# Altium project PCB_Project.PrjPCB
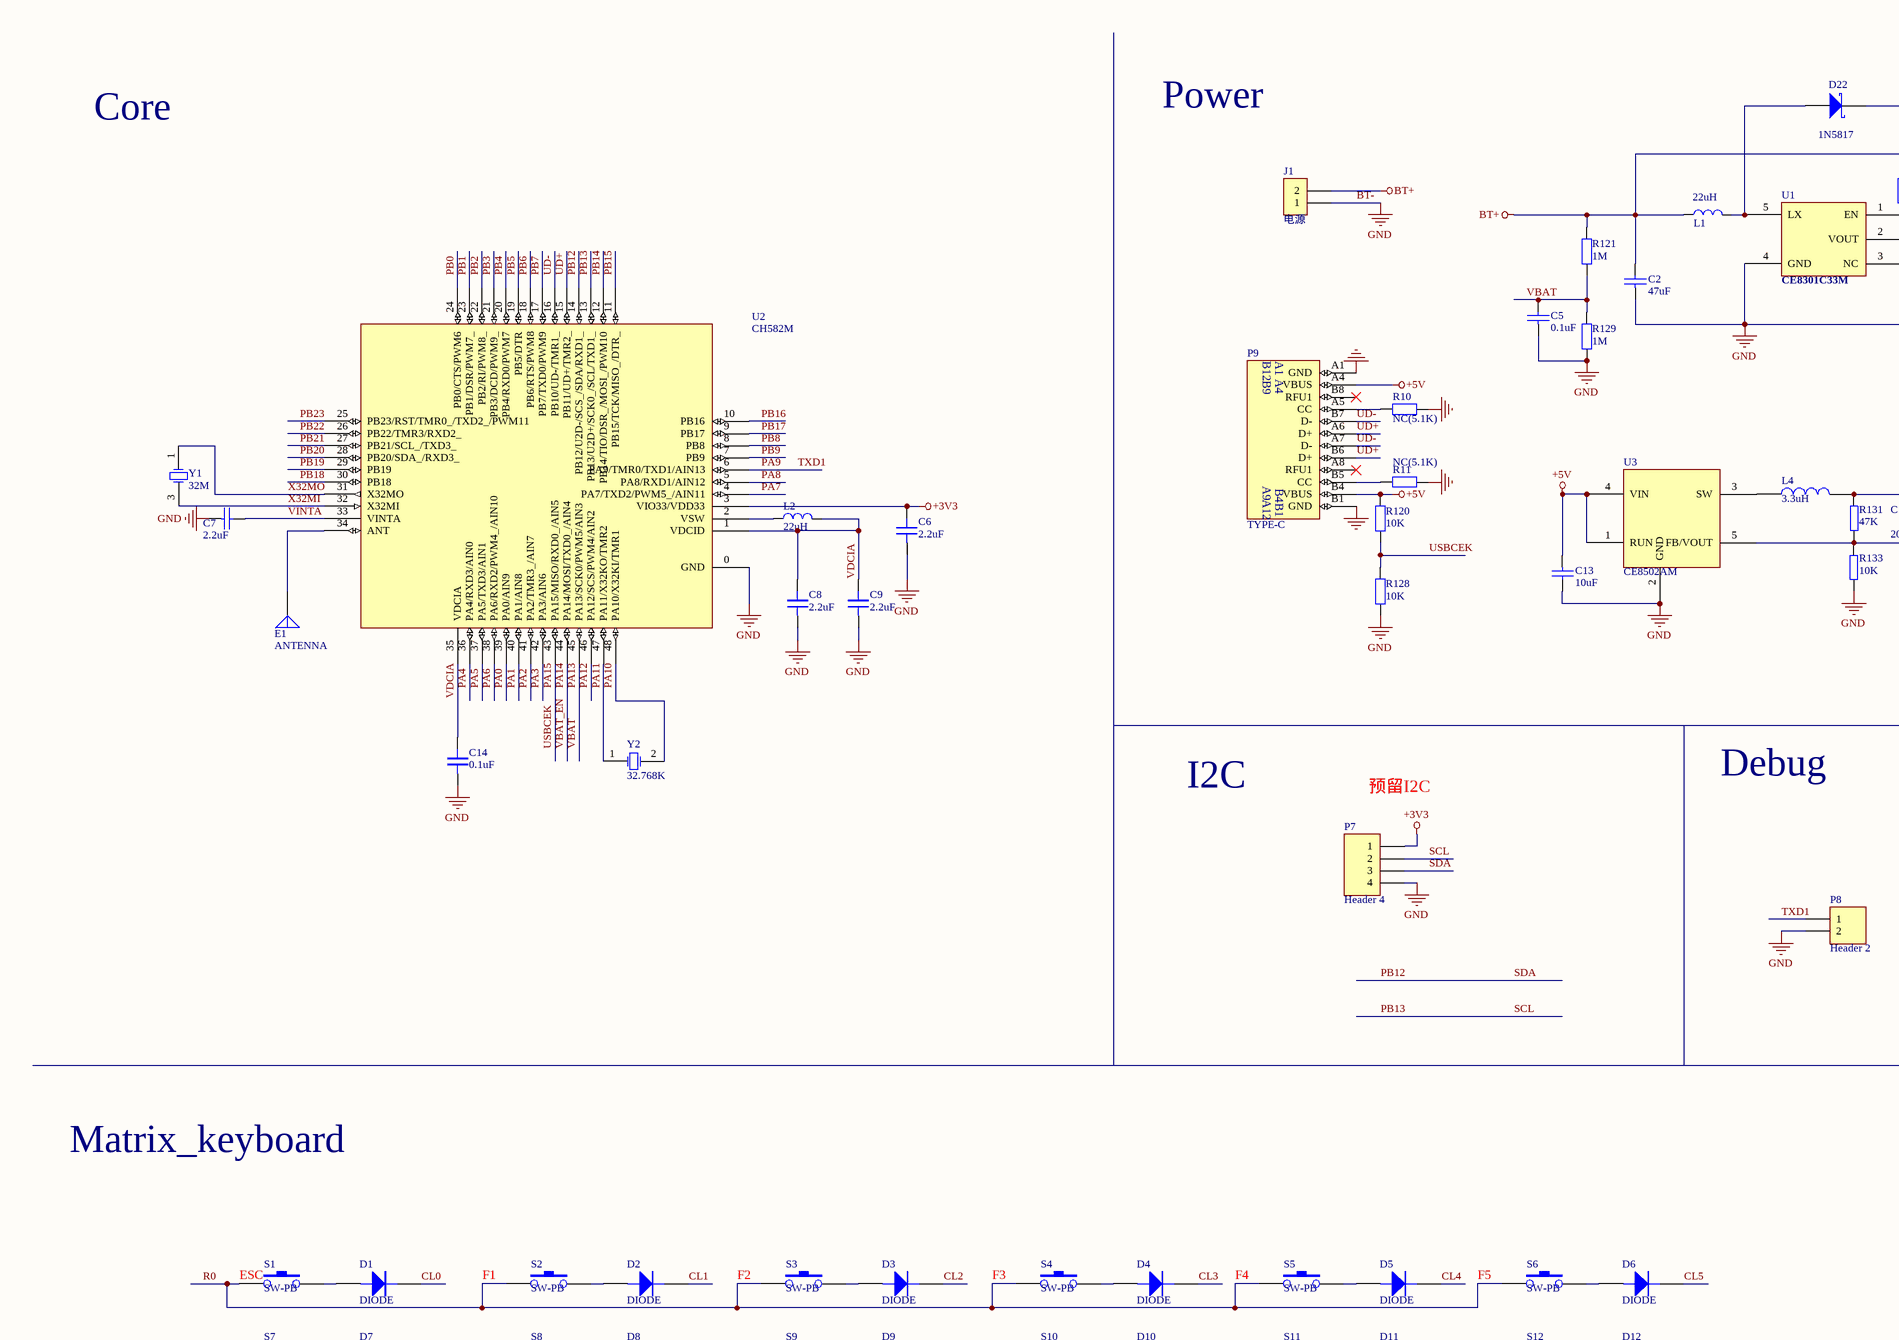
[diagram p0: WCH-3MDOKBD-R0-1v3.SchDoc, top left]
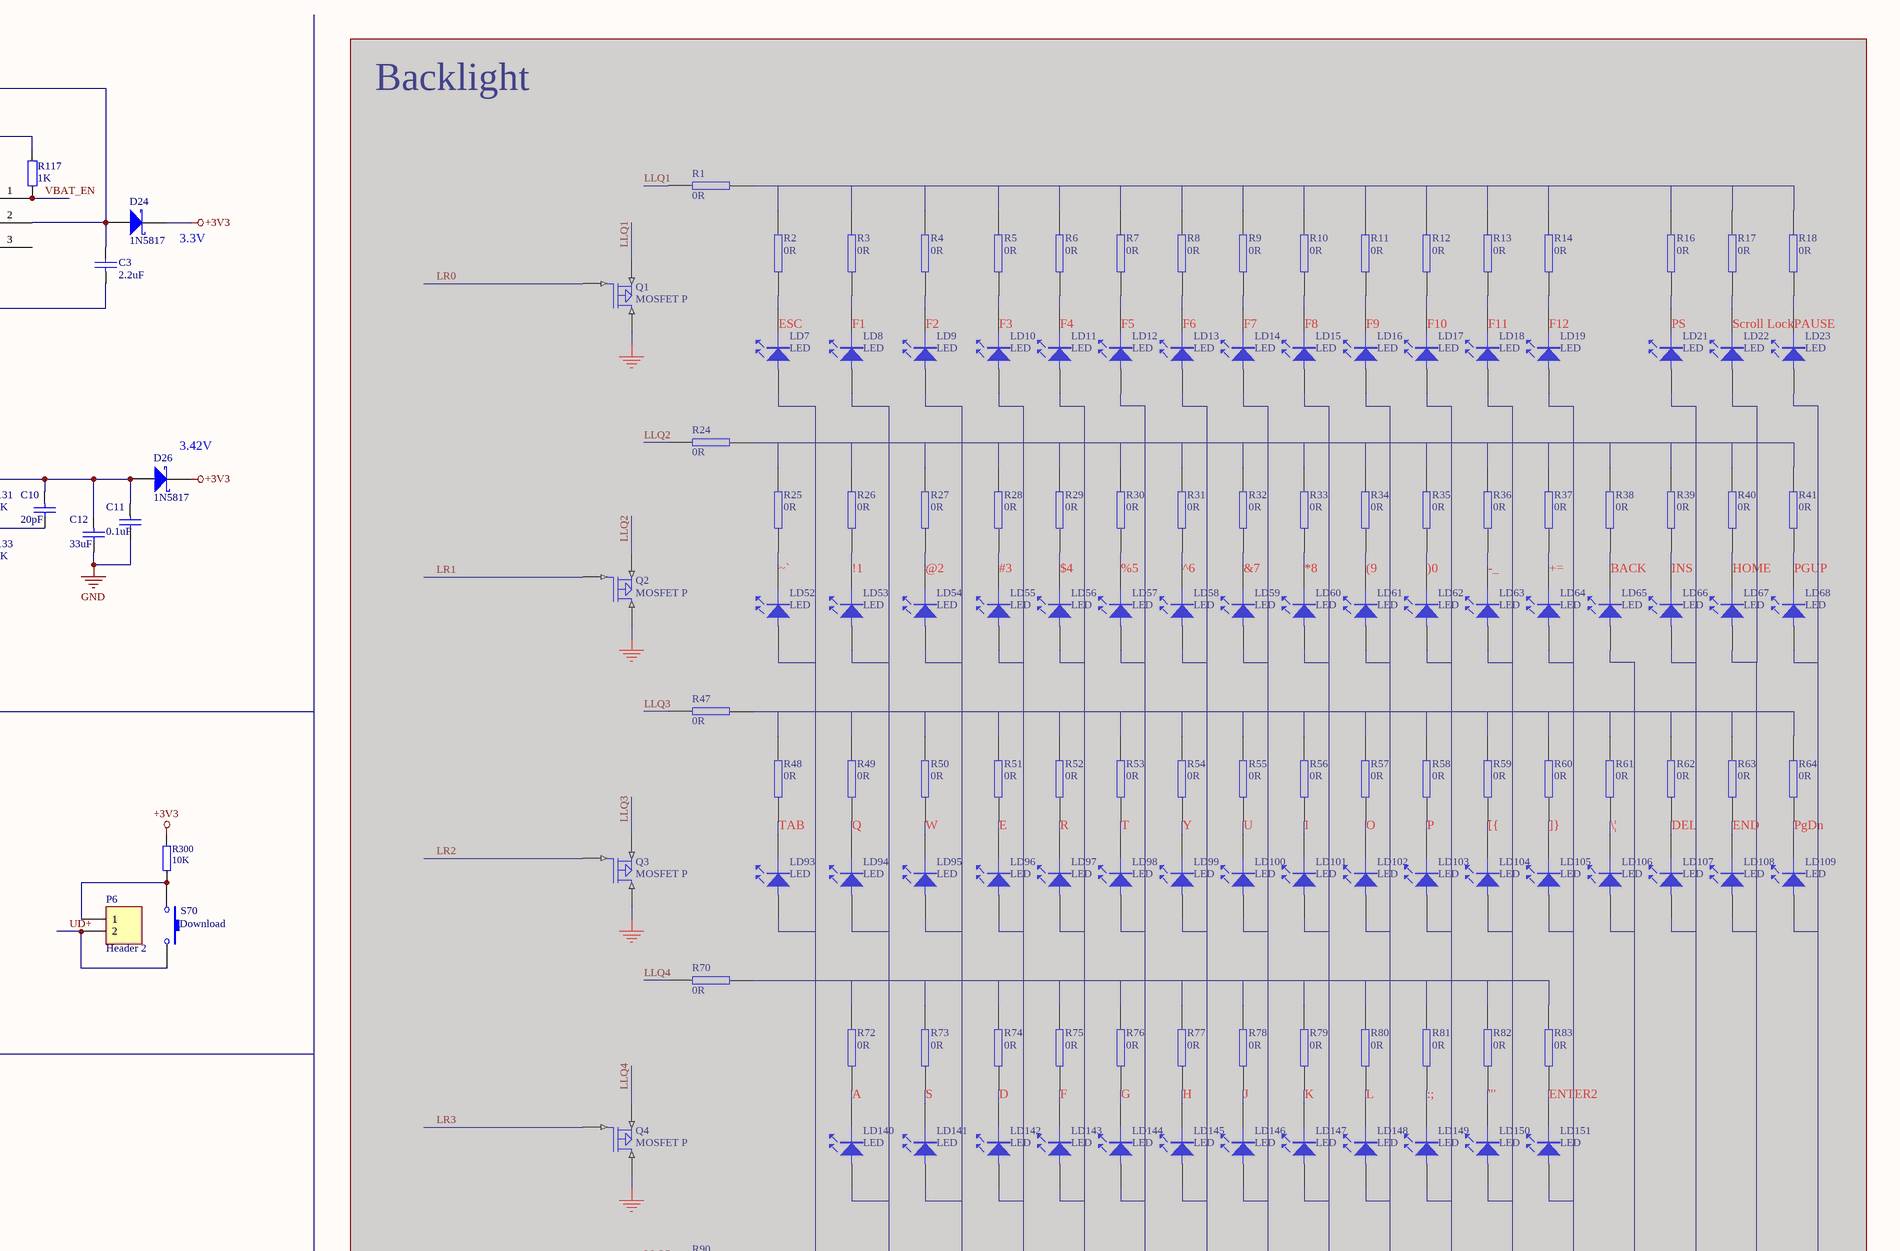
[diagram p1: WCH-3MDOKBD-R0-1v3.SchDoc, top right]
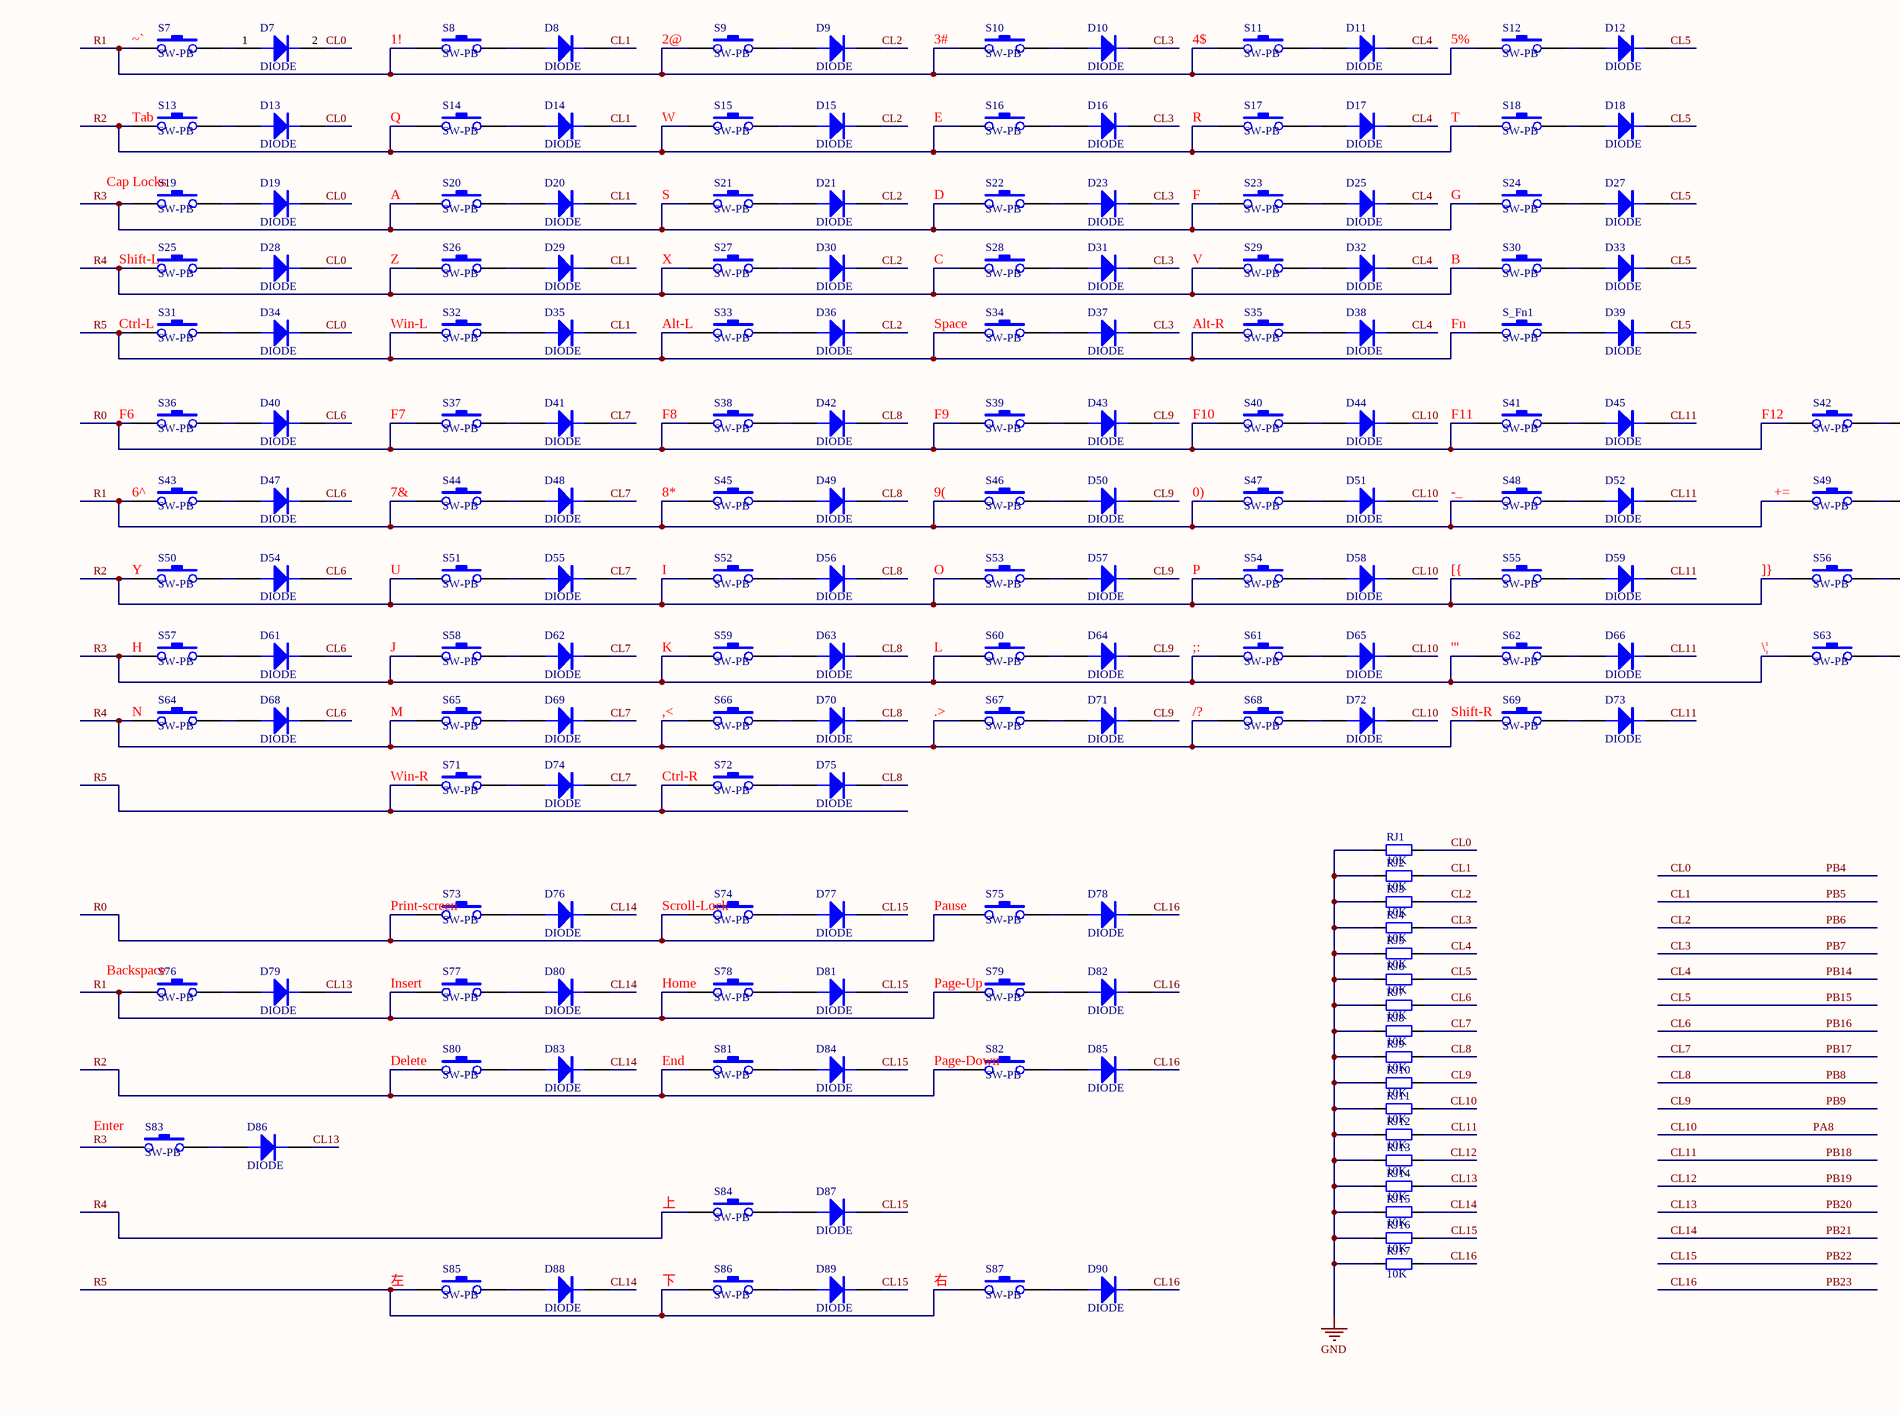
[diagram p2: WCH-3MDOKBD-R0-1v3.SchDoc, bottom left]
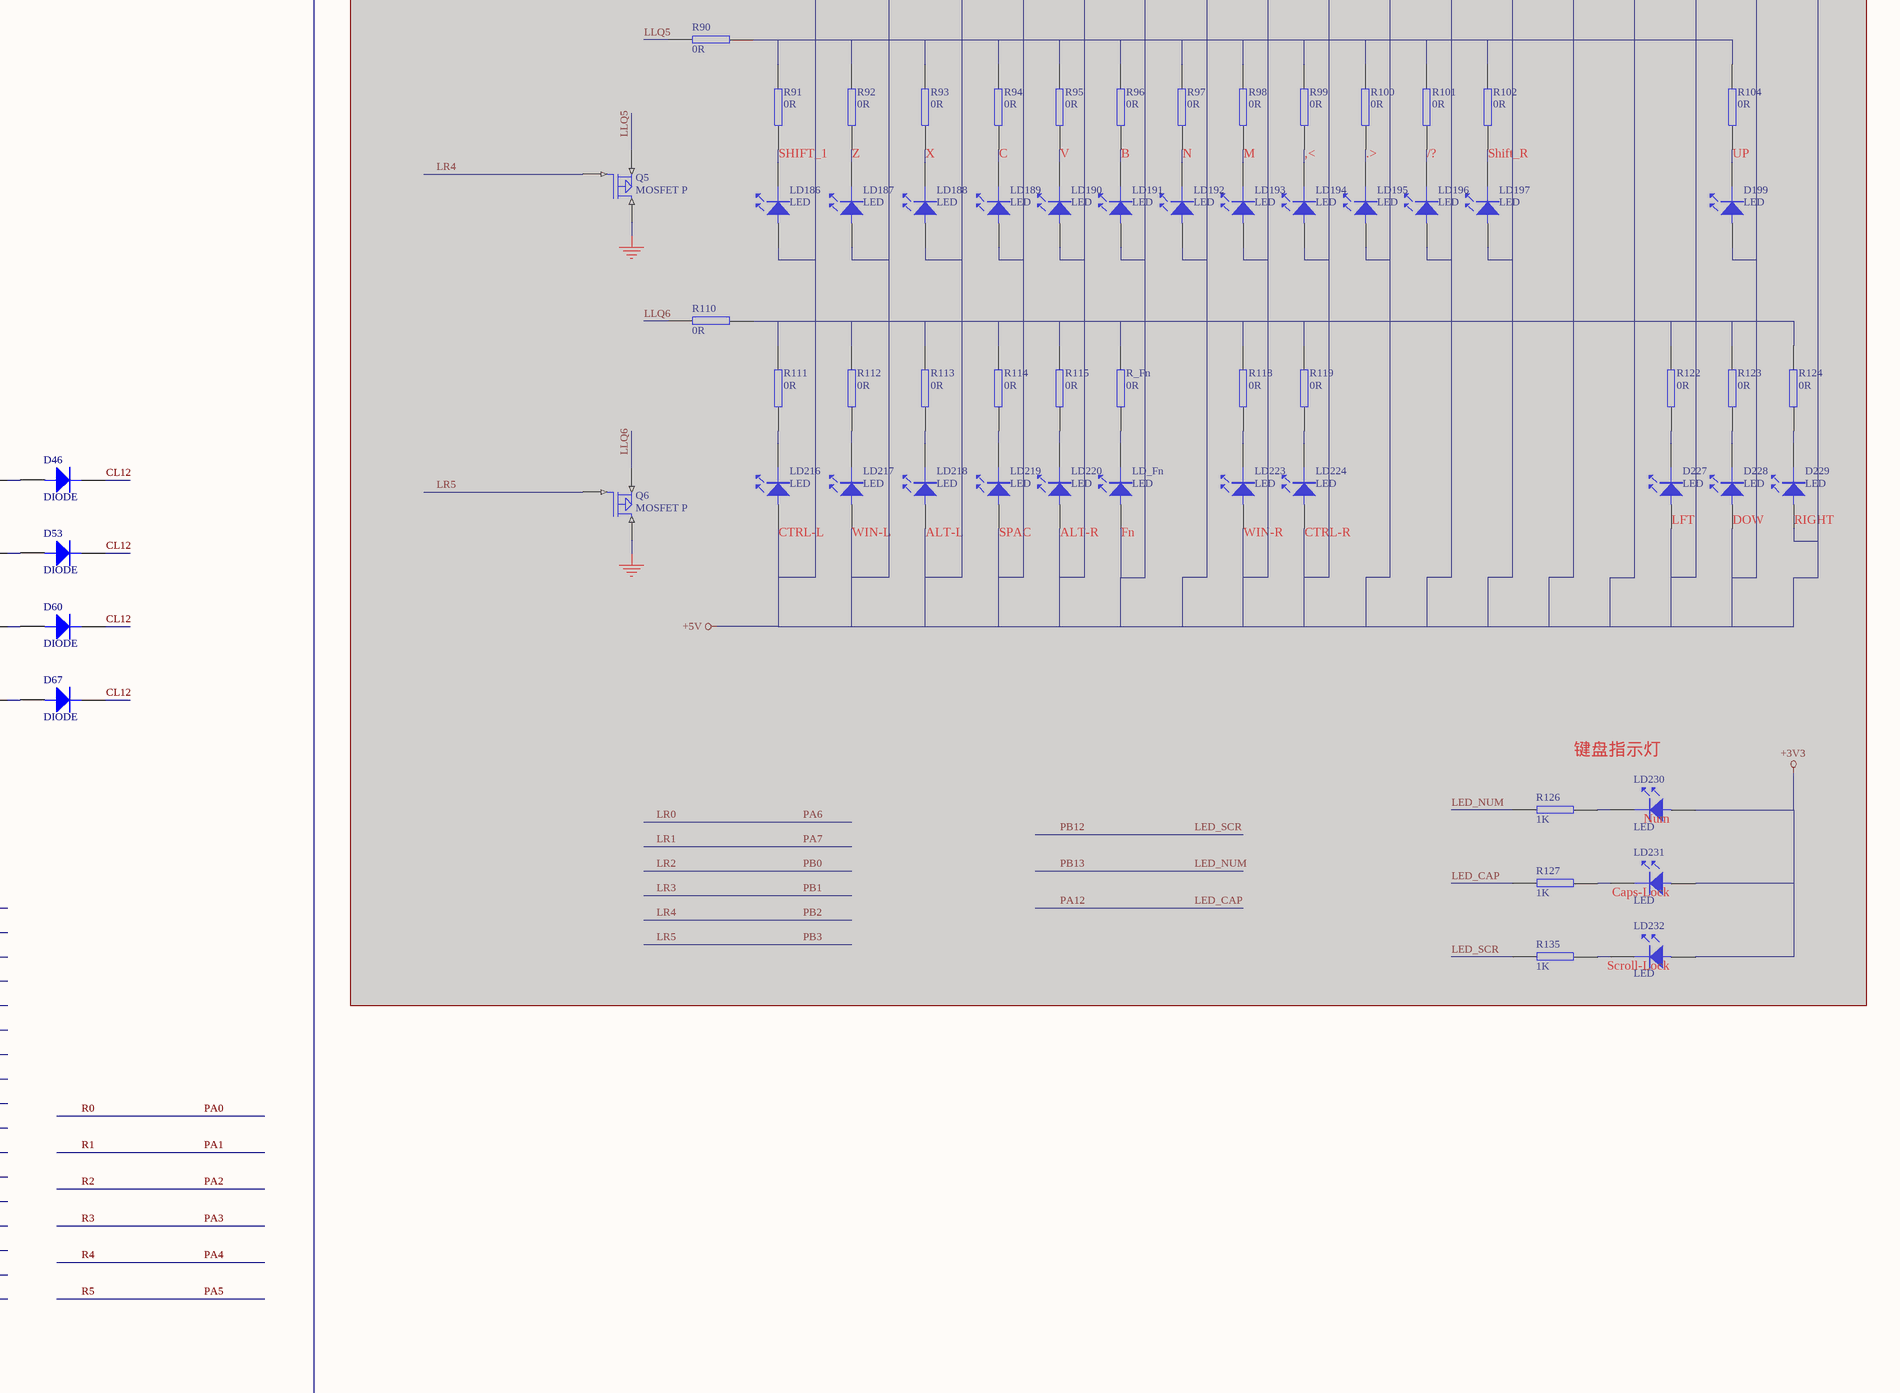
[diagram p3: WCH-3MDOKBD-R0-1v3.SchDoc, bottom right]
1 sheet, 421 parts. Net scope: global (net labels, ports and power ports of the same name join across sheets).
Board file: WCH-3MDOKBD-R0-1v3.PcbDoc

## Sheet WCH-3MDOKBD-R0-1v3.SchDoc
size A1

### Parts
(Parts that share a designator on the sheet are numbered #1, #2 ... from top to bottom, then left to right.)
C2  47uF  [3528_C]
C3  2.2uF  [0402_C]
C5  0.1uF  [0402_C]
C6  2.2uF  [0603_C]
C7  2.2uF  [0402_C]
C8  2.2uF  [0603_C]
C9  2.2uF  [0603_C]
C10  20pF  [0603_C]
C11  0.1uF  [0603_C]
C12  33uF  [3528_C]
C13  10uF  [3216_C]
C14  0.1uF  [0603_C]
D1  DIODE  [3216+]
D2  DIODE  [3216+]
D3  DIODE  [3216+]
D4  DIODE  [3216+]
D5  DIODE  [3216+]
D6  DIODE  [3216+]
D7  DIODE  [3216+]
D8  DIODE  [3216+]
D9  DIODE  [3216+]
D10  DIODE  [3216+]
D11  DIODE  [3216+]
D12  DIODE  [3216+]
D13  DIODE  [3216+]
D14  DIODE  [3216+]
D15  DIODE  [3216+]
D16  DIODE  [3216+]
D17  DIODE  [3216+]
D18  DIODE  [3216+]
D19  DIODE  [3216+]
D20  DIODE  [3216+]
D21  DIODE  [3216+]
D22  1N5817  [7227+]
D23  DIODE  [3216+]
D24  1N5817  [7227+]
D25  DIODE  [3216+]
D26  1N5817  [7227+]
D27  DIODE  [3216+]
D28  DIODE  [3216+]
D29  DIODE  [3216+]
D30  DIODE  [3216+]
D31  DIODE  [3216+]
D32  DIODE  [3216+]
D33  DIODE  [3216+]
D34  DIODE  [3216+]
D35  DIODE  [3216+]
D36  DIODE  [3216+]
D37  DIODE  [3216+]
D38  DIODE  [3216+]
D39  DIODE  [3216+]
D40  DIODE  [3216+]
D41  DIODE  [3216+]
D42  DIODE  [3216+]
D43  DIODE  [3216+]
D44  DIODE  [3216+]
D45  DIODE  [3216+]
D46  DIODE  [3216+]
D47  DIODE  [3216+]
D48  DIODE  [3216+]
D49  DIODE  [3216+]
D50  DIODE  [3216+]
D51  DIODE  [3216+]
D52  DIODE  [3216+]
D53  DIODE  [3216+]
D54  DIODE  [3216+]
D55  DIODE  [3216+]
D56  DIODE  [3216+]
D57  DIODE  [3216+]
D58  DIODE  [3216+]
D59  DIODE  [3216+]
D60  DIODE  [3216+]
D61  DIODE  [3216+]
D62  DIODE  [3216+]
D63  DIODE  [3216+]
D64  DIODE  [3216+]
D65  DIODE  [3216+]
D66  DIODE  [3216+]
D67  DIODE  [3216+]
D68  DIODE  [3216+]
D69  DIODE  [3216+]
D70  DIODE  [3216+]
D71  DIODE  [3216+]
D72  DIODE  [3216+]
D73  DIODE  [3216+]
D74  DIODE  [3216+]
D75  DIODE  [3216+]
D76  DIODE  [3216+]
D77  DIODE  [3216+]
D78  DIODE  [3216+]
D79  DIODE  [3216+]
D80  DIODE  [3216+]
D81  DIODE  [3216+]
D82  DIODE  [3216+]
D83  DIODE  [3216+]
D84  DIODE  [3216+]
D85  DIODE  [3216+]
D86  DIODE  [3216+]
D87  DIODE  [3216+]
D88  DIODE  [3216+]
D89  DIODE  [3216+]
D90  DIODE  [3216+]
D199  LED  [0603+]  (masked out: inside a compile mask, not in the netlist)
D227  LED  [0603+]  (masked out: inside a compile mask, not in the netlist)
D228  LED  [0603+]  (masked out: inside a compile mask, not in the netlist)
D229  LED  [0603+]  (masked out: inside a compile mask, not in the netlist)
E1  ANTENNA  [ANT-F-1-2.4G-1.6]
J1  电源  [SIP2-2.54mm]
L1  22uH  [SMD_7.3x7.8mm]
L2  22uH  [SMD_2x2mm]
L4  3.3uH  [SMD_5x5mm]
LD7  LED  [0603+]  (masked out: inside a compile mask, not in the netlist)
LD8  LED  [0603+]  (masked out: inside a compile mask, not in the netlist)
LD9  LED  [0603+]  (masked out: inside a compile mask, not in the netlist)
LD10  LED  [0603+]  (masked out: inside a compile mask, not in the netlist)
LD11  LED  [0603+]  (masked out: inside a compile mask, not in the netlist)
LD12  LED  [0603+]  (masked out: inside a compile mask, not in the netlist)
LD13  LED  [0603+]  (masked out: inside a compile mask, not in the netlist)
LD14  LED  [0603+]  (masked out: inside a compile mask, not in the netlist)
LD15  LED  [0603+]  (masked out: inside a compile mask, not in the netlist)
LD16  LED  [0603+]  (masked out: inside a compile mask, not in the netlist)
LD17  LED  [0603+]  (masked out: inside a compile mask, not in the netlist)
LD18  LED  [0603+]  (masked out: inside a compile mask, not in the netlist)
LD19  LED  [0603+]  (masked out: inside a compile mask, not in the netlist)
LD21  LED  [0603+]  (masked out: inside a compile mask, not in the netlist)
LD22  LED  [0603+]  (masked out: inside a compile mask, not in the netlist)
LD23  LED  [0603+]  (masked out: inside a compile mask, not in the netlist)
LD52  LED  [0603+]  (masked out: inside a compile mask, not in the netlist)
LD53  LED  [0603+]  (masked out: inside a compile mask, not in the netlist)
LD54  LED  [0603+]  (masked out: inside a compile mask, not in the netlist)
LD55  LED  [0603+]  (masked out: inside a compile mask, not in the netlist)
LD56  LED  [0603+]  (masked out: inside a compile mask, not in the netlist)
LD57  LED  [0603+]  (masked out: inside a compile mask, not in the netlist)
LD58  LED  [0603+]  (masked out: inside a compile mask, not in the netlist)
LD59  LED  [0603+]  (masked out: inside a compile mask, not in the netlist)
LD60  LED  [0603+]  (masked out: inside a compile mask, not in the netlist)
LD61  LED  [0603+]  (masked out: inside a compile mask, not in the netlist)
LD62  LED  [0603+]  (masked out: inside a compile mask, not in the netlist)
LD63  LED  [0603+]  (masked out: inside a compile mask, not in the netlist)
LD64  LED  [0603+]  (masked out: inside a compile mask, not in the netlist)
LD65  LED  [0603+]  (masked out: inside a compile mask, not in the netlist)
LD66  LED  [0603+]  (masked out: inside a compile mask, not in the netlist)
LD67  LED  [0603+]  (masked out: inside a compile mask, not in the netlist)
LD68  LED  [0603+]  (masked out: inside a compile mask, not in the netlist)
LD93  LED  [0603+]  (masked out: inside a compile mask, not in the netlist)
LD94  LED  [0603+]  (masked out: inside a compile mask, not in the netlist)
LD95  LED  [0603+]  (masked out: inside a compile mask, not in the netlist)
LD96  LED  [0603+]  (masked out: inside a compile mask, not in the netlist)
LD97  LED  [0603+]  (masked out: inside a compile mask, not in the netlist)
LD98  LED  [0603+]  (masked out: inside a compile mask, not in the netlist)
LD99  LED  [0603+]  (masked out: inside a compile mask, not in the netlist)
LD100  LED  [0603+]  (masked out: inside a compile mask, not in the netlist)
LD101  LED  [0603+]  (masked out: inside a compile mask, not in the netlist)
LD102  LED  [0603+]  (masked out: inside a compile mask, not in the netlist)
LD103  LED  [0603+]  (masked out: inside a compile mask, not in the netlist)
LD104  LED  [0603+]  (masked out: inside a compile mask, not in the netlist)
LD105  LED  [0603+]  (masked out: inside a compile mask, not in the netlist)
LD106  LED  [0603+]  (masked out: inside a compile mask, not in the netlist)
LD107  LED  [0603+]  (masked out: inside a compile mask, not in the netlist)
LD108  LED  [0603+]  (masked out: inside a compile mask, not in the netlist)
LD109  LED  [0603+]  (masked out: inside a compile mask, not in the netlist)
LD140  LED  [0603+]  (masked out: inside a compile mask, not in the netlist)
LD141  LED  [0603+]  (masked out: inside a compile mask, not in the netlist)
LD142  LED  [0603+]  (masked out: inside a compile mask, not in the netlist)
LD143  LED  [0603+]  (masked out: inside a compile mask, not in the netlist)
LD144  LED  [0603+]  (masked out: inside a compile mask, not in the netlist)
LD145  LED  [0603+]  (masked out: inside a compile mask, not in the netlist)
LD146  LED  [0603+]  (masked out: inside a compile mask, not in the netlist)
LD147  LED  [0603+]  (masked out: inside a compile mask, not in the netlist)
LD148  LED  [0603+]  (masked out: inside a compile mask, not in the netlist)
LD149  LED  [0603+]  (masked out: inside a compile mask, not in the netlist)
LD150  LED  [0603+]  (masked out: inside a compile mask, not in the netlist)
LD151  LED  [0603+]  (masked out: inside a compile mask, not in the netlist)
LD186  LED  [0603+]  (masked out: inside a compile mask, not in the netlist)
LD187  LED  [0603+]  (masked out: inside a compile mask, not in the netlist)
LD188  LED  [0603+]  (masked out: inside a compile mask, not in the netlist)
LD189  LED  [0603+]  (masked out: inside a compile mask, not in the netlist)
LD190  LED  [0603+]  (masked out: inside a compile mask, not in the netlist)
LD191  LED  [0603+]  (masked out: inside a compile mask, not in the netlist)
LD192  LED  [0603+]  (masked out: inside a compile mask, not in the netlist)
LD193  LED  [0603+]  (masked out: inside a compile mask, not in the netlist)
LD194  LED  [0603+]  (masked out: inside a compile mask, not in the netlist)
LD195  LED  [0603+]  (masked out: inside a compile mask, not in the netlist)
LD196  LED  [0603+]  (masked out: inside a compile mask, not in the netlist)
LD197  LED  [0603+]  (masked out: inside a compile mask, not in the netlist)
LD216  LED  [0603+]  (masked out: inside a compile mask, not in the netlist)
LD217  LED  [0603+]  (masked out: inside a compile mask, not in the netlist)
LD218  LED  [0603+]  (masked out: inside a compile mask, not in the netlist)
LD219  LED  [0603+]  (masked out: inside a compile mask, not in the netlist)
LD220  LED  [0603+]  (masked out: inside a compile mask, not in the netlist)
LD223  LED  [0603+]  (masked out: inside a compile mask, not in the netlist)
LD224  LED  [0603+]  (masked out: inside a compile mask, not in the netlist)
LD230  LED  [0603+]  (masked out: inside a compile mask, not in the netlist)
LD231  LED  [0603+]  (masked out: inside a compile mask, not in the netlist)
LD232  LED  [0603+]  (masked out: inside a compile mask, not in the netlist)
LD_Fn  LED  [0603+]  (masked out: inside a compile mask, not in the netlist)
P6  Header 2  [SIP2-2.54mm]
P7  Header 4  [HDR1X4]
P8  Header 2  [SIP2-2.54mm]
P9  TYPE-C  [TYPE-C-Receptacle-2.0]
Q1  MOSFET P  [SOT-23]  (masked out: inside a compile mask, not in the netlist)
Q2  MOSFET P  [SOT-23]  (masked out: inside a compile mask, not in the netlist)
Q3  MOSFET P  [SOT-23]  (masked out: inside a compile mask, not in the netlist)
Q4  MOSFET P  [SOT-23]  (masked out: inside a compile mask, not in the netlist)
Q5  MOSFET P  [SOT-23]  (masked out: inside a compile mask, not in the netlist)
Q6  MOSFET P  [SOT-23]  (masked out: inside a compile mask, not in the netlist)
R1  0R  [0603]  (masked out: inside a compile mask, not in the netlist)
R2  0R  [0603]  (masked out: inside a compile mask, not in the netlist)
R3  0R  [0603]  (masked out: inside a compile mask, not in the netlist)
R4  0R  [0603]  (masked out: inside a compile mask, not in the netlist)
R5  0R  [0603]  (masked out: inside a compile mask, not in the netlist)
R6  0R  [0603]  (masked out: inside a compile mask, not in the netlist)
R7  0R  [0603]  (masked out: inside a compile mask, not in the netlist)
R8  0R  [0603]  (masked out: inside a compile mask, not in the netlist)
R9  0R  [0603]  (masked out: inside a compile mask, not in the netlist)
R10#1  0R  [0603]  (masked out: inside a compile mask, not in the netlist)
R10#2  NC(5.1K)  [0603]
R11#1  0R  [0603]  (masked out: inside a compile mask, not in the netlist)
R11#2  NC(5.1K)  [0603]
R12  0R  [0603]  (masked out: inside a compile mask, not in the netlist)
R13  0R  [0603]  (masked out: inside a compile mask, not in the netlist)
R14  0R  [0603]  (masked out: inside a compile mask, not in the netlist)
R16  0R  [0603]  (masked out: inside a compile mask, not in the netlist)
R17  0R  [0603]  (masked out: inside a compile mask, not in the netlist)
R18  0R  [0603]  (masked out: inside a compile mask, not in the netlist)
R24  0R  [0603]  (masked out: inside a compile mask, not in the netlist)
R25  0R  [0603]  (masked out: inside a compile mask, not in the netlist)
R26  0R  [0603]  (masked out: inside a compile mask, not in the netlist)
R27  0R  [0603]  (masked out: inside a compile mask, not in the netlist)
R28  0R  [0603]  (masked out: inside a compile mask, not in the netlist)
R29  0R  [0603]  (masked out: inside a compile mask, not in the netlist)
R30  0R  [0603]  (masked out: inside a compile mask, not in the netlist)
R31  0R  [0603]  (masked out: inside a compile mask, not in the netlist)
R32  0R  [0603]  (masked out: inside a compile mask, not in the netlist)
R33  0R  [0603]  (masked out: inside a compile mask, not in the netlist)
R34  0R  [0603]  (masked out: inside a compile mask, not in the netlist)
R35  0R  [0603]  (masked out: inside a compile mask, not in the netlist)
R36  0R  [0603]  (masked out: inside a compile mask, not in the netlist)
R37  0R  [0603]  (masked out: inside a compile mask, not in the netlist)
R38  0R  [0603]  (masked out: inside a compile mask, not in the netlist)
R39  0R  [0603]  (masked out: inside a compile mask, not in the netlist)
R40  0R  [0603]  (masked out: inside a compile mask, not in the netlist)
R41  0R  [0603]  (masked out: inside a compile mask, not in the netlist)
R47  0R  [0603]  (masked out: inside a compile mask, not in the netlist)
R48  0R  [0603]  (masked out: inside a compile mask, not in the netlist)
R49  0R  [0603]  (masked out: inside a compile mask, not in the netlist)
R50  0R  [0603]  (masked out: inside a compile mask, not in the netlist)
R51  0R  [0603]  (masked out: inside a compile mask, not in the netlist)
R52  0R  [0603]  (masked out: inside a compile mask, not in the netlist)
R53  0R  [0603]  (masked out: inside a compile mask, not in the netlist)
R54  0R  [0603]  (masked out: inside a compile mask, not in the netlist)
R55  0R  [0603]  (masked out: inside a compile mask, not in the netlist)
R56  0R  [0603]  (masked out: inside a compile mask, not in the netlist)
R57  0R  [0603]  (masked out: inside a compile mask, not in the netlist)
R58  0R  [0603]  (masked out: inside a compile mask, not in the netlist)
R59  0R  [0603]  (masked out: inside a compile mask, not in the netlist)
R60  0R  [0603]  (masked out: inside a compile mask, not in the netlist)
R61  0R  [0603]  (masked out: inside a compile mask, not in the netlist)
R62  0R  [0603]  (masked out: inside a compile mask, not in the netlist)
R63  0R  [0603]  (masked out: inside a compile mask, not in the netlist)
R64  0R  [0603]  (masked out: inside a compile mask, not in the netlist)
R70  0R  [0603]  (masked out: inside a compile mask, not in the netlist)
R72  0R  [0603]  (masked out: inside a compile mask, not in the netlist)
R73  0R  [0603]  (masked out: inside a compile mask, not in the netlist)
R74  0R  [0603]  (masked out: inside a compile mask, not in the netlist)
R75  0R  [0603]  (masked out: inside a compile mask, not in the netlist)
R76  0R  [0603]  (masked out: inside a compile mask, not in the netlist)
R77  0R  [0603]  (masked out: inside a compile mask, not in the netlist)
R78  0R  [0603]  (masked out: inside a compile mask, not in the netlist)
R79  0R  [0603]  (masked out: inside a compile mask, not in the netlist)
R80  0R  [0603]  (masked out: inside a compile mask, not in the netlist)
R81  0R  [0603]  (masked out: inside a compile mask, not in the netlist)
R82  0R  [0603]  (masked out: inside a compile mask, not in the netlist)
R83  0R  [0603]  (masked out: inside a compile mask, not in the netlist)
R90  0R  [0603]  (masked out: inside a compile mask, not in the netlist)
R91  0R  [0603]  (masked out: inside a compile mask, not in the netlist)
R92  0R  [0603]  (masked out: inside a compile mask, not in the netlist)
R93  0R  [0603]  (masked out: inside a compile mask, not in the netlist)
R94  0R  [0603]  (masked out: inside a compile mask, not in the netlist)
R95  0R  [0603]  (masked out: inside a compile mask, not in the netlist)
R96  0R  [0603]  (masked out: inside a compile mask, not in the netlist)
R97  0R  [0603]  (masked out: inside a compile mask, not in the netlist)
R98  0R  [0603]  (masked out: inside a compile mask, not in the netlist)
R99  0R  [0603]  (masked out: inside a compile mask, not in the netlist)
R100  0R  [0603]  (masked out: inside a compile mask, not in the netlist)
R101  0R  [0603]  (masked out: inside a compile mask, not in the netlist)
R102  0R  [0603]  (masked out: inside a compile mask, not in the netlist)
R104  0R  [0603]  (masked out: inside a compile mask, not in the netlist)
R110  0R  [0603]  (masked out: inside a compile mask, not in the netlist)
R111  0R  [0603]  (masked out: inside a compile mask, not in the netlist)
R112  0R  [0603]  (masked out: inside a compile mask, not in the netlist)
R113  0R  [0603]  (masked out: inside a compile mask, not in the netlist)
R114  0R  [0603]  (masked out: inside a compile mask, not in the netlist)
R115  0R  [0603]  (masked out: inside a compile mask, not in the netlist)
R117  1K  [0603]
R118  0R  [0603]  (masked out: inside a compile mask, not in the netlist)
R119  0R  [0603]  (masked out: inside a compile mask, not in the netlist)
R120  10K  [0603]
R121  1M  [0603]
R122  0R  [0603]  (masked out: inside a compile mask, not in the netlist)
R123  0R  [0603]  (masked out: inside a compile mask, not in the netlist)
R124  0R  [0603]  (masked out: inside a compile mask, not in the netlist)
R126  1K  [0603]  (masked out: inside a compile mask, not in the netlist)
R127  1K  [0603]  (masked out: inside a compile mask, not in the netlist)
R128  10K  [0603]
R129  1M  [0603]
R131  47K  [0603]
R133  10K  [0603]
R135  1K  [0603]  (masked out: inside a compile mask, not in the netlist)
R300  10K  [0603]
R_Fn  0R  [0603]  (masked out: inside a compile mask, not in the netlist)
RJ1  10K  [0603]
RJ2  10K  [0603]
RJ3  10K  [0603]
RJ4  10K  [0603]
RJ5  10K  [0603]
RJ6  10K  [0603]
RJ7  10K  [0603]
RJ8  10K  [0603]
RJ9  10K  [0603]
RJ10  10K  [0603]
RJ11  10K  [0603]
RJ12  10K  [0603]
RJ13  10K  [0603]
RJ14  10K  [0603]
RJ15  10K  [0603]
RJ16  10K  [0603]
RJ17  10K  [0603]
S1  SW-PB  [SMD_6.1x3.65x2.5mm-KEY]
S2  SW-PB  [SMD_6.1x3.65x2.5mm-KEY]
S3  SW-PB  [SMD_6.1x3.65x2.5mm-KEY]
S4  SW-PB  [SMD_6.1x3.65x2.5mm-KEY]
S5  SW-PB  [SMD_6.1x3.65x2.5mm-KEY]
S6  SW-PB  [SMD_6.1x3.65x2.5mm-KEY]
S7  SW-PB  [SMD_6.1x3.65x2.5mm-KEY]
S8  SW-PB  [SMD_6.1x3.65x2.5mm-KEY]
S9  SW-PB  [SMD_6.1x3.65x2.5mm-KEY]
S10  SW-PB  [SMD_6.1x3.65x2.5mm-KEY]
S11  SW-PB  [SMD_6.1x3.65x2.5mm-KEY]
S12  SW-PB  [SMD_6.1x3.65x2.5mm-KEY]
S13  SW-PB  [SMD_6.1x3.65x2.5mm-KEY]
S14  SW-PB  [SMD_6.1x3.65x2.5mm-KEY]
S15  SW-PB  [SMD_6.1x3.65x2.5mm-KEY]
S16  SW-PB  [SMD_6.1x3.65x2.5mm-KEY]
S17  SW-PB  [SMD_6.1x3.65x2.5mm-KEY]
S18  SW-PB  [SMD_6.1x3.65x2.5mm-KEY]
S19  SW-PB  [SMD_6.1x3.65x2.5mm-KEY]
S20  SW-PB  [SMD_6.1x3.65x2.5mm-KEY]
S21  SW-PB  [SMD_6.1x3.65x2.5mm-KEY]
S22  SW-PB  [SMD_6.1x3.65x2.5mm-KEY]
S23  SW-PB  [SMD_6.1x3.65x2.5mm-KEY]
S24  SW-PB  [SMD_6.1x3.65x2.5mm-KEY]
S25  SW-PB  [SMD_6.1x3.65x2.5mm-KEY]
S26  SW-PB  [SMD_6.1x3.65x2.5mm-KEY]
S27  SW-PB  [SMD_6.1x3.65x2.5mm-KEY]
S28  SW-PB  [SMD_6.1x3.65x2.5mm-KEY]
S29  SW-PB  [SMD_6.1x3.65x2.5mm-KEY]
S30  SW-PB  [SMD_6.1x3.65x2.5mm-KEY]
S31  SW-PB  [SMD_6.1x3.65x2.5mm-KEY]
S32  SW-PB  [SMD_6.1x3.65x2.5mm-KEY]
S33  SW-PB  [SMD_6.1x3.65x2.5mm-KEY]
S34  SW-PB  [SMD_6.1x3.65x2.5mm-KEY]
S35  SW-PB  [SMD_6.1x3.65x2.5mm-KEY]
S36  SW-PB  [SMD_6.1x3.65x2.5mm-KEY]
S37  SW-PB  [SMD_6.1x3.65x2.5mm-KEY]
S38  SW-PB  [SMD_6.1x3.65x2.5mm-KEY]
S39  SW-PB  [SMD_6.1x3.65x2.5mm-KEY]
S40  SW-PB  [SMD_6.1x3.65x2.5mm-KEY]
S41  SW-PB  [SMD_6.1x3.65x2.5mm-KEY]
S42  SW-PB  [SMD_6.1x3.65x2.5mm-KEY]
S43  SW-PB  [SMD_6.1x3.65x2.5mm-KEY]
S44  SW-PB  [SMD_6.1x3.65x2.5mm-KEY]
S45  SW-PB  [SMD_6.1x3.65x2.5mm-KEY]
S46  SW-PB  [SMD_6.1x3.65x2.5mm-KEY]
S47  SW-PB  [SMD_6.1x3.65x2.5mm-KEY]
S48  SW-PB  [SMD_6.1x3.65x2.5mm-KEY]
S49  SW-PB  [SMD_6.1x3.65x2.5mm-KEY]
S50  SW-PB  [SMD_6.1x3.65x2.5mm-KEY]
S51  SW-PB  [SMD_6.1x3.65x2.5mm-KEY]
S52  SW-PB  [SMD_6.1x3.65x2.5mm-KEY]
S53  SW-PB  [SMD_6.1x3.65x2.5mm-KEY]
S54  SW-PB  [SMD_6.1x3.65x2.5mm-KEY]
S55  SW-PB  [SMD_6.1x3.65x2.5mm-KEY]
S56  SW-PB  [SMD_6.1x3.65x2.5mm-KEY]
S57  SW-PB  [SMD_6.1x3.65x2.5mm-KEY]
S58  SW-PB  [SMD_6.1x3.65x2.5mm-KEY]
S59  SW-PB  [SMD_6.1x3.65x2.5mm-KEY]
S60  SW-PB  [SMD_6.1x3.65x2.5mm-KEY]
S61  SW-PB  [SMD_6.1x3.65x2.5mm-KEY]
S62  SW-PB  [SMD_6.1x3.65x2.5mm-KEY]
S63  SW-PB  [SMD_6.1x3.65x2.5mm-KEY]
S64  SW-PB  [SMD_6.1x3.65x2.5mm-KEY]
S65  SW-PB  [SMD_6.1x3.65x2.5mm-KEY]
S66  SW-PB  [SMD_6.1x3.65x2.5mm-KEY]
S67  SW-PB  [SMD_6.1x3.65x2.5mm-KEY]
S68  SW-PB  [SMD_6.1x3.65x2.5mm-KEY]
S69  SW-PB  [SMD_6.1x3.65x2.5mm-KEY]
S70  Download  [贴片按键]
S71  SW-PB  [SMD_6.1x3.65x2.5mm-KEY]
S72  SW-PB  [SMD_6.1x3.65x2.5mm-KEY]
S73  SW-PB  [SMD_6.1x3.65x2.5mm-KEY]
S74  SW-PB  [SMD_6.1x3.65x2.5mm-KEY]
S75  SW-PB  [SMD_6.1x3.65x2.5mm-KEY]
S76  SW-PB  [SMD_6.1x3.65x2.5mm-KEY]
S77  SW-PB  [SMD_6.1x3.65x2.5mm-KEY]
S78  SW-PB  [SMD_6.1x3.65x2.5mm-KEY]
S79  SW-PB  [SMD_6.1x3.65x2.5mm-KEY]
S80  SW-PB  [SMD_6.1x3.65x2.5mm-KEY]
S81  SW-PB  [SMD_6.1x3.65x2.5mm-KEY]
S82  SW-PB  [SMD_6.1x3.65x2.5mm-KEY]
S83  SW-PB  [SMD_6.1x3.65x2.5mm-KEY]
S84  SW-PB  [SMD_6.1x3.65x2.5mm-KEY]
S85  SW-PB  [SMD_6.1x3.65x2.5mm-KEY]
S86  SW-PB  [SMD_6.1x3.65x2.5mm-KEY]
S87  SW-PB  [SMD_6.1x3.65x2.5mm-KEY]
S_Fn1  SW-PB  [SMD_6.1x3.65x2.5mm-KEY]
U1  CE8301C33M  [SOT-23-5]
U2  CH582M  [QFN48_5X5]
U3  CE8502AM  [SOT-23-5]
Y1  32M  [XT3225]
Y2  32.768K  [FC-135]

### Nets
+3V3: C6.2 D24.2(K) D26.2(K) P7.1 R300.2 U2.3(VIO33/VDD33)
+5V: C13.1 P9.A4(VBUS) P9.B4(VBUS) R120.2 U3.1(RUN) U3.4(VIN)
BT+: C2.2 J1.2 L1.1 R117.2 R121.2
BT-: C2.1 C3.1 C5.1 C6.1 C7.1 C8.1 C9.1 C11.2 C12.2 C13.2 C14.1 J1.1 P7.4 P8.2 P9.A1(GND) P9.B1(GND) R10#2.2 R11#2.2 R128.1 R129.1 R133.1 RJ1.1 RJ2.1 RJ3.1 RJ4.1 RJ5.1 RJ6.1 RJ7.1 RJ8.1 RJ9.1 RJ10.1 RJ11.1 RJ12.1 RJ13.1 RJ14.1 RJ15.1 RJ16.1 RJ17.1 U1.4(GND) U2.0(GND) U3.2(GND)  [also labelled GND]
CL0: D1.2(K) D7.2(K) D13.2(K) D19.2(K) D28.2(K) D34.2(K) RJ1.2 U2.20(PB4/RXD0/PWM7)  [also labelled PB4]
CL1: D2.2(K) D8.2(K) D14.2(K) D20.2(K) D29.2(K) D35.2(K) RJ2.2 U2.19(PB5/DTR)  [also labelled PB5]
CL2: D3.2(K) D9.2(K) D15.2(K) D21.2(K) D30.2(K) D36.2(K) RJ3.2 U2.18(PB6/RTS/PWM8)  [also labelled PB6]
CL3: D4.2(K) D10.2(K) D16.2(K) D23.2(K) D31.2(K) D37.2(K) RJ4.2 U2.17(PB7/TXD0/PWM9)  [also labelled PB7]
CL4: D5.2(K) D11.2(K) D17.2(K) D25.2(K) D32.2(K) D38.2(K) RJ5.2 U2.12(PB14/TIO/DSR_/MOSI_/PWM10)  [also labelled PB14]
CL5: D6.2(K) D12.2(K) D18.2(K) D27.2(K) D33.2(K) D39.2(K) RJ6.2 U2.11(PB15/TCK/MISO_/DTR_)  [also labelled PB15]
CL6: D40.2(K) D47.2(K) D54.2(K) D61.2(K) D68.2(K) RJ7.2 U2.10(PB16)  [also labelled PB16]
CL7: D41.2(K) D48.2(K) D55.2(K) D62.2(K) D69.2(K) D74.2(K) RJ8.2 U2.9(PB17)  [also labelled PB17]
CL8: D42.2(K) D49.2(K) D56.2(K) D63.2(K) D70.2(K) D75.2(K) RJ9.2 U2.8(PB8)  [also labelled PB8]
CL9: D43.2(K) D50.2(K) D57.2(K) D64.2(K) D71.2(K) RJ10.2 U2.7(PB9)  [also labelled PB9]
CL10: D44.2(K) D51.2(K) D58.2(K) D65.2(K) D72.2(K) RJ11.2 U2.5(PA8/RXD1/AIN12)  [also labelled PA8]
CL11: D45.2(K) D52.2(K) D59.2(K) D66.2(K) D73.2(K) RJ12.2 U2.30(PB18)  [also labelled PB18]
CL12: D46.2(K) D53.2(K) D60.2(K) D67.2(K) RJ13.2 U2.29(PB19)  [also labelled PB19]
CL13: D79.2(K) D86.2(K) RJ14.2 U2.28(PB20/SDA_/RXD3_)  [also labelled PB20]
CL14: D76.2(K) D80.2(K) D83.2(K) D88.2(K) RJ15.2 U2.27(PB21/SCL_/TXD3_)  [also labelled PB21]
CL15: D77.2(K) D81.2(K) D84.2(K) D87.2(K) D89.2(K) RJ16.2 U2.26(PB22/TMR3/RXD2_)  [also labelled PB22]
CL16: D78.2(K) D82.2(K) D85.2(K) D90.2(K) RJ17.2 U2.25(PB23/RST/TMR0_/TXD2_/PWM11)  [also labelled PB23]
PA0: S1.1 S2.1 S3.1 S4.1 S5.1 S6.1 S36.1 S37.1 S38.1 S39.1 S40.1 S41.1 S42.1 S73.1 S74.1 S75.1 U2.39(PA0/AIN9)  [also labelled R0]
PA1: S7.1 S8.1 S9.1 S10.1 S11.1 S12.1 S43.1 S44.1 S45.1 S46.1 S47.1 S48.1 S49.1 S76.1 S77.1 S78.1 S79.1 U2.40(PA1/AIN8)  [also labelled R1]
PA2: S13.1 S14.1 S15.1 S16.1 S17.1 S18.1 S50.1 S51.1 S52.1 S53.1 S54.1 S55.1 S56.1 S80.1 S81.1 S82.1 U2.41(PA2/TMR3_/AIN7)  [also labelled R2]
PA3: S19.1 S20.1 S21.1 S22.1 S23.1 S24.1 S57.1 S58.1 S59.1 S60.1 S61.1 S62.1 S63.1 S83.1 U2.42(PA3/AIN6)  [also labelled R3]
PA4: S25.1 S26.1 S27.1 S28.1 S29.1 S30.1 S64.1 S65.1 S66.1 S67.1 S68.1 S69.1 S84.1 U2.36(PA4/RXD3/AIN0)  [also labelled R4]
PA5: S31.1 S32.1 S33.1 S34.1 S35.1 S71.1 S72.1 S85.1 S86.1 S87.1 S_Fn1.1 U2.37(PA5/TXD3/AIN1)  [also labelled R5]
PA6: U2.38(PA6/RXD2/PWM4_/AIN10)
PA7: U2.4(PA7/TXD2/PWM5_/AIN11)
PA9: P8.1 U2.6(PA9/TMR0/TXD1/AIN13)  [also labelled TXD1]
PA10: U2.48(PA10/X32KI/TMR1) Y2.2(OSC2)
PA11: U2.47(PA11/X32KO/TMR2) Y2.1(OSC1)
PA12: U2.46(PA12/SCS/PWM4/AIN2)
PA13: C5.2 R121.1 R129.2 U2.45(PA13/SCK0/PWM5/AIN3)  [also labelled VBAT]
PA14: R117.1 U1.1(EN) U2.44(PA14/MOSI/TXD0_/AIN4)  [also labelled VBAT_EN]
PA15: R120.1 R128.2 U2.43(PA15/MISO/RXD0_/AIN5)  [also labelled USBCEK]
PB0: U2.24(PB0/CTS/PWM6)
PB1: U2.23(PB1/DSR/PWM7_)
PB2: U2.22(PB2/RI/PWM8_)
PB3: U2.21(PB3/DCD/PWM9_)
PB12: P7.3 U2.14(PB12/U2D-/SCS_/SDA/RXD1_)  [also labelled SDA]
PB13: P7.2 U2.13(PB13/U2D+/SCK0_/SCL/TXD1_)  [also labelled SCL]
UD+: P6.2 P9.A6(D+) P9.B6(D+) S70.3 U2.15(PB11/UD+/TMR2_)
UD-: P9.A7(D-) P9.B7(D-) U2.16(PB10/UD-/TMR1_)
VDCIA: C8.2 C9.2 C14.2 L2.2 U2.1(VDCID) U2.35(VDCIA)
VINTA: C7.2 U2.33(VINTA)
X32MI: U2.32(X32MI) Y1.3(OSC2)
X32MO: U2.31(X32MO) Y1.1(OSC1)
NetC3_2: C3.2 D22.2(K) D24.1(A) U1.2(VOUT)
NetC10_1: C10.1 C11.1 C12.1 D26.1(A) L4.2 R131.1
NetC10_2: C10.2 R131.2 R133.2 U3.5(FB/VOUT)
NetD1_1: D1.1(A) S1.2
NetD2_1: D2.1(A) S2.2
NetD3_1: D3.1(A) S3.2
NetD4_1: D4.1(A) S4.2
NetD5_1: D5.1(A) S5.2
NetD6_1: D6.1(A) S6.2
NetD7_1: D7.1(A) S7.2
NetD8_1: D8.1(A) S8.2
NetD9_1: D9.1(A) S9.2
NetD10_1: D10.1(A) S10.2
NetD11_1: D11.1(A) S11.2
NetD12_1: D12.1(A) S12.2
NetD13_1: D13.1(A) S13.2
NetD14_1: D14.1(A) S14.2
NetD15_1: D15.1(A) S15.2
NetD16_1: D16.1(A) S16.2
NetD17_1: D17.1(A) S17.2
NetD18_1: D18.1(A) S18.2
NetD19_1: D19.1(A) S19.2
NetD20_1: D20.1(A) S20.2
NetD21_1: D21.1(A) S21.2
NetD22_1: D22.1(A) L1.2 U1.5(LX)
NetD23_1: D23.1(A) S22.2
NetD25_1: D25.1(A) S23.2
NetD27_1: D27.1(A) S24.2
NetD28_1: D28.1(A) S25.2
NetD29_1: D29.1(A) S26.2
NetD30_1: D30.1(A) S27.2
NetD31_1: D31.1(A) S28.2
NetD32_1: D32.1(A) S29.2
NetD33_1: D33.1(A) S30.2
NetD34_1: D34.1(A) S31.2
NetD35_1: D35.1(A) S32.2
NetD36_1: D36.1(A) S33.2
NetD37_1: D37.1(A) S34.2
NetD38_1: D38.1(A) S35.2
NetD39_1: D39.1(A) S_Fn1.2
NetD40_1: D40.1(A) S36.2
NetD41_1: D41.1(A) S37.2
NetD42_1: D42.1(A) S38.2
NetD43_1: D43.1(A) S39.2
NetD44_1: D44.1(A) S40.2
NetD45_1: D45.1(A) S41.2
NetD46_1: D46.1(A) S42.2
NetD47_1: D47.1(A) S43.2
NetD48_1: D48.1(A) S44.2
NetD49_1: D49.1(A) S45.2
NetD50_1: D50.1(A) S46.2
NetD51_1: D51.1(A) S47.2
NetD52_1: D52.1(A) S48.2
NetD53_1: D53.1(A) S49.2
NetD54_1: D54.1(A) S50.2
NetD55_1: D55.1(A) S51.2
NetD56_1: D56.1(A) S52.2
NetD57_1: D57.1(A) S53.2
NetD58_1: D58.1(A) S54.2
NetD59_1: D59.1(A) S55.2
NetD60_1: D60.1(A) S56.2
NetD61_1: D61.1(A) S57.2
NetD62_1: D62.1(A) S58.2
NetD63_1: D63.1(A) S59.2
NetD64_1: D64.1(A) S60.2
NetD65_1: D65.1(A) S61.2
NetD66_1: D66.1(A) S62.2
NetD67_1: D67.1(A) S63.2
NetD68_1: D68.1(A) S64.2
NetD69_1: D69.1(A) S65.2
NetD70_1: D70.1(A) S66.2
NetD71_1: D71.1(A) S67.2
NetD72_1: D72.1(A) S68.2
NetD73_1: D73.1(A) S69.2
NetD74_1: D74.1(A) S71.2
NetD75_1: D75.1(A) S72.2
NetD76_1: D76.1(A) S73.2
NetD77_1: D77.1(A) S74.2
NetD78_1: D78.1(A) S75.2
NetD79_1: D79.1(A) S76.2
NetD80_1: D80.1(A) S77.2
NetD81_1: D81.1(A) S78.2
NetD82_1: D82.1(A) S79.2
NetD83_1: D83.1(A) S80.2
NetD84_1: D84.1(A) S81.2
NetD85_1: D85.1(A) S82.2
NetD86_1: D86.1(A) S83.2
NetD87_1: D87.1(A) S84.2
NetD88_1: D88.1(A) S85.2
NetD89_1: D89.1(A) S86.2
NetD90_1: D90.1(A) S87.2
NetE1_1: E1.1(A) U2.34(ANT)
NetL2_1: L2.1 U2.2(VSW)
NetL4_1: L4.1 U3.3(SW)
NetP6_1: P6.1 R300.1 S70.1
NetP9_A5: P9.A5(CC) R10#2.1
NetP9_B5: P9.B5(CC) R11#2.1

Not connected (* = marked no-connect by the designer): P9 A8(RFU1)* B8(RFU1)*; U1 3(NC)

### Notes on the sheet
- Power
- Backlight
- Core
- (near D24) 3.3V
- (near LD7) ESC
- (near LD8) F1
- (near LD9) F2
- (near LD10) F3
- (near LD11) F4
- (near LD12) F5
- (near LD13) F6
- (near LD14) F7
- (near LD15) F8
- (near LD16) F9
- (near LD17) F10
- (near LD18) F11
- (near LD19) F12
- (near LD21) PS
- Scroll Lock
- (near LD23) PAUSE
- (near D26) 3.42V
- (near U3) Hot!!!
- (near LD52) ~`
- (near LD53) !1
- (near LD54) @2
- (near LD55) #3
- (near LD56) $4
- (near LD57) %5
- (near LD58) ^6
- (near LD59) &7
- (near LD60) *8
- (near LD61) (9
- (near LD62) )0
- (near LD63) -_
- (near LD64) +=
- (near LD65) BACK
- (near LD66) INS
- (near LD67) HOME
- (near LD68) PGUP
- Debug
- I2C
- 预留I2C
- TAB
- Q
- W
- E
- R
- T
- Y
- U
- I
- O
- P
- [{
- ]}
- \¦
- DEL
- END
- PgDn
- A
- S
- D
- F
- G
- H
- J
- K
- L
- :;
- "'
- ENTER2
- Matrix_keyboard
- (near S1) ESC
- (near S2) F1
- (near S3) F2
- (near S4) F3
- (near S5) F4
- (near S6) F5
- (near S7) ~`
- (near S8) 1!
- (near S9) 2@
- (near S10) 3#
- (near S11) 4$
- (near S12) 5%
- SHIFT_1
- Z
- X
- C
- V
- B
- N
- M
- ,<
- .>
- /?
- Shift_R
- UP
- (near S13) Tab
- (near S14) Q
- (near S15) W
- (near S16) E
- (near S19) Cap Locks
- (near S20) A
- (near S21) S
- (near S22) D
- (near S25) Shift-L
- (near S31) Ctrl-L
- (near S32) Win-L
- (near S33) Alt-L
- (near S34) Space
- (near S35) Alt-R
- (near S_Fn1) Fn
- (near S36) F6
- (near S37) F7
- (near S38) F8
- (near S39) F9
- (near S40) F10
- (near S41) F11
- (near S42) F12
- (near D227) LFT
- (near D228) DOW
- (near D229) RIGHT
- (near S43) 6^
- (near S44) 7&
- (near S45) 8*
- (near S46) 9(
- (near S47) 0)
- (near S48) -_
- (near S49) +=
- (near LD216) CTRL-L
- (near LD217) WIN-L
- (near LD218) ALT-L
- (near LD219) SPAC
- ALT-R
- (near LD_Fn) Fn
- WIN-R
- (near LD224) CTRL-R
- (near S50) Y
- (near S51) U
- (near S52) I
- (near S53) O
- (near S55) [{
- (near S56) ]}
- (near S57) H
- (near S58) J
- (near S59) K
- (near S60) L
- (near S61) ;:
- (near S62) '"
- (near S63) \¦
- (near S64) N
- (near S66) ,<
- (near S67) .>
- (near S68) /?
- (near S69) Shift-R
- 键盘指示灯
- (near S71) Win-R
- (near S72) Ctrl-R
- (near LD230) Num
- (near LD231) Caps-Lock
- (near S73) Print-screen
- (near S74) Scroll-Lock
- (near S75) Pause
- (near LD232) Scroll-Lock
- (near S76) Backspace
- (near S77) Insert
- (near S78) Home
- (near S79) Page-Up
- (near S80) Delete
- (near S81) End
- (near S82) Page-Down
- (near S83) Enter
- (near S84) 上
- (near S85) 左
- (near S86) 下
- (near S87) 右

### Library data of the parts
C2 C3 C5 C7 = C0402
C6 C8-C14 = CAP: Capacitor
D22 D24 D26 = D Schottky: Schottky Diode
E1 = ANTENNA: Generic Antenna
J1 = HDR1x2: Connector
L1 = 1.05.0226.04: 物料名称: 电感; Value2: 额定电流600mA; Value3: 顺络
L2 = INDUCTANCE
L4 = INDUCTOR
P6 P8 = Header 2: Header, 2-Pin
P7 = Header 4: Header, 4-Pin
P9 = TYPE-C1
R1-R9 R10#1 R11#1 R12-R14 R16-R18 R24-R41 R47-R64 R70 R72-R83 R90-R102 R104 R110-R115 R118 R119 R122-R124 R126 R127 R135 R_Fn = RES2
R10#2 R11#2 RJ1-RJ17 = Res2: Resistor
R117 R120 R121 R128 R129 = RES: Resistor
R131 R133 = R
R300 = DZ
S70 = SW-PB: Switch
U1 = 1.07.0021.05: 物料名称: IC
U2 = CH582M: RISC-V MCU with BLE/2*USB/ADC/PWM/SPI/I2C/4*UART
U3 = FP6160
Y1 Y2 = XTAL: Crystal Oscillator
